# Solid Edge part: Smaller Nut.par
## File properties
Author: m_hel
Template: iso metric part.par
Last saved by: m_hel
Revision: 2
Application: Solid Edge
Accuracy: 0,990
Username: m_hel
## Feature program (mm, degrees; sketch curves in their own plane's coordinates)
sketch for "unnamed Protrusion 1" plane through (0, 0, 0) normal (0, 0, 1) x-axis (1, 0, 0)
  line (-8.6603, -15) -> (8.6603, -15)
  line (8.6603, -15) -> (17.3205, 0)
  line (17.3205, 0) -> (8.6603, 15)
  line (8.6603, 15) -> (-8.6603, 15)
  line (-8.6603, 15) -> (-17.3205, 0)
  line (-17.3205, 0) -> (-8.6603, -15)
extrude "unnamed Protrusion 1" add finite 15 along +normal
sketch for "Hole_1" plane through (0, 0, 15) normal (0, 0, 1) x-axis (1, 0, 0)
  hole centre (0, 0) bore radius 10
hole "Hole_1" diameter 20 through
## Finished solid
Body 1: solid body, 9 faces, 20 edges, 12 vertices.
  Faces by surface: plane 8, cylinder 1
  Edges by curve: line 18, circle 2
Bounding box of the edges (mm): 34.641 x 30.000 x 15.000, from (-17.3205, -15, 0) to (17.3205, 15, 15).
Cylindrical faces by radius (mm): R10 x1
Planar faces by outward normal: +y 1, +z 1, -y 1, -z 1, oblique 4
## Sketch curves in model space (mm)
circle centre (0, 0, 0) radius 15
line (-17.3205, 0, 0) -> (-8.6603, -15, 0)
line (-8.6603, -15, 0) -> (8.6603, -15, 0)
line (8.6603, -15, 0) -> (17.3205, 0, 0)
line (17.3205, 0, 0) -> (8.6603, 15, 0)
line (8.6603, 15, 0) -> (-8.6603, 15, 0)
line (-8.6603, 15, 0) -> (-17.3205, 0, 0)
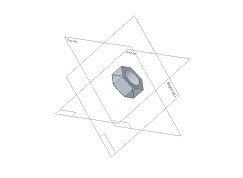
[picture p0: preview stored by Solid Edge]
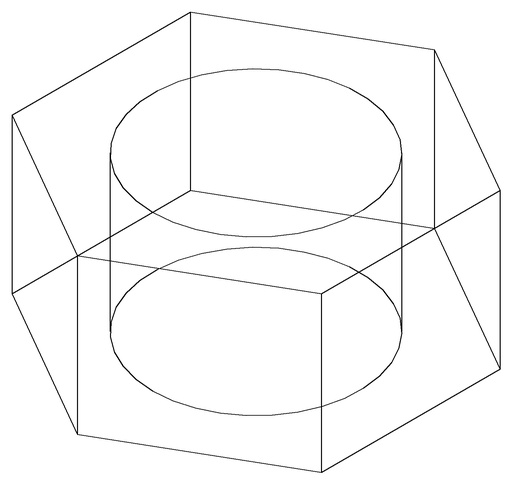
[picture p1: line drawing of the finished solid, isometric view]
